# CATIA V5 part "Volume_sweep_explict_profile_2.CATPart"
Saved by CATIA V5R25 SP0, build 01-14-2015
Part number: Part1
Bounding box of the stored display mesh (mm): x -0.369 to 107.282, y -258.392 to 1.309, z -19.937 to 111.99
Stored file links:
  E:\cadcim\GSD_cat_v5-6r2014\Part_files\Volume_sweep_explict_profile_2.CATPart
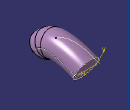
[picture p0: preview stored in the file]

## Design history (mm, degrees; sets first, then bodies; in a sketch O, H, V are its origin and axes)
Set1
  Sketch1 on yz-plane, origin (0, 0, 0), H (0, 1, 0), V (0, 0, 1)
    spline S1 through (-23.0016, 27.4581) (-75.0426, 47.0094) (-171.9366, 48.7346) (-214.202, 27.4581)
  Plane1: type Offset, RefPlane yz-plane, Offset 107
  Sketch2 on Plane1, origin (107, 0, 0), H (0, 1, 0), V (0, 0, 1)
    spline S1 through (-23.0016, 27.4581) (-104.0993, 55.4238) (-183.694, 56.9883) (-214.202, 27.4581)
    reference projected point E1 (-214.202, 27.4581) from vertex of Sketch1
    reference projected point E2 (-23.0016, 27.4581) from vertex of Sketch1
    point P1 (-214.202, 27.4581)
    point P2 (-23.0016, 27.4581)
    coincidence: P1 E1, P2 E2
  Plane2: type Normal, Curve Sketch1, RefPoint vertex of Sketch1, Ratio 0
  Sketch3 on Plane2, origin (0, -29.3756, 14.8457), H (1, 0, 0), V (0, 0.451, 0.8925)
    circle A1 centre (53.5, 14.5287) radius 53.5015
    reference projected point E1 (107, 14.1316) from Sketch2.P2
    reference projected point E2 (0, 14.1316) from vertex of Sketch1
    coincidence: A1 E1, A1 E2
  Sketch4 on Plane2, origin (0, -29.3756, 14.8457), H (1, 0, 0), V (0, 0.451, 0.8925)
    point P1 (107, 14.1316)
    reference projected point E1 (107, 14.1316) from Sketch2.P2
    coincidence: P1 E1
  Sketch5 on Plane2, origin (0, -29.3756, 14.8457), H (1, 0, 0), V (0, 0.451, 0.8925)
    point P1 (0, 14.1316)
    reference projected point E1 (0, 14.1316) from vertex of Sketch1
    coincidence: P1 E1
  Sweep1: type Unspec, Profile Sketch3, Guide (Sketch2; Sketch1), FittingPoints (Sketch4; Sketch5)
Body1 (main body)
